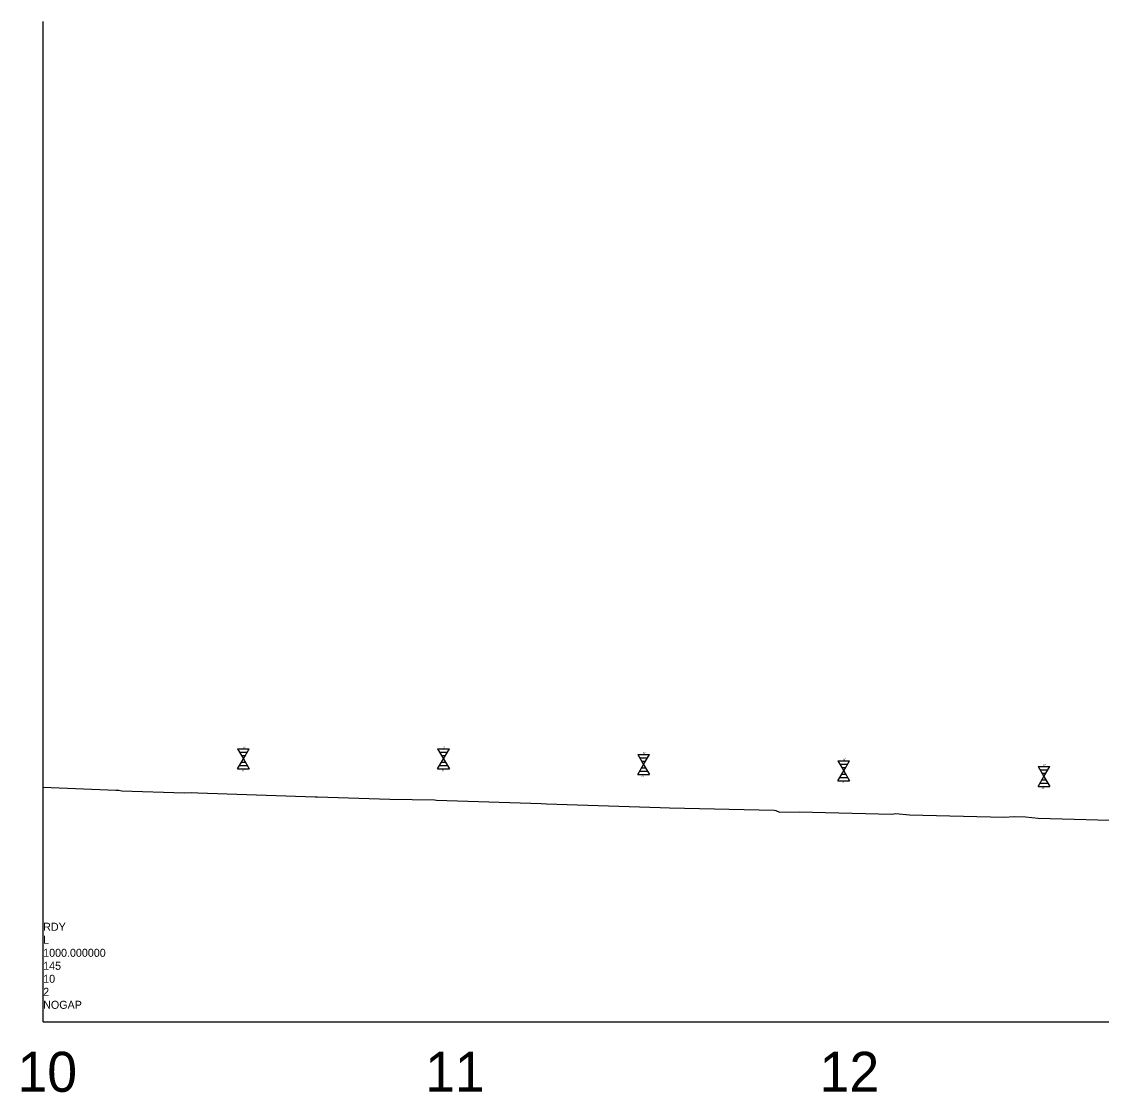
# Model space of a CAD drawing. Extents: x 573468 to 580768, y -57414 to -51768.
# Drawn here: x 573759.8 to 574029.6, y -53116.2 to -52848.5 of the extents above; entities that cross this region are included whole.
import ezdxf

# ---------------------------------------------------------------- set-up
doc = ezdxf.new("R2010")
doc.units = 0
for name, color, linetype in [('Exist Profile Cell', 7, 'Continuous'), ('Exist Vertical Profile Ground Line', 7, 'Continuous'), ('Exist Vertical Profile Horizontal Axis Label Major', 7, 'Continuous'), ('Scratch_Level_0', 7, 'Continuous')]:
    doc.layers.add(name, color=color, linetype=linetype)

msp = doc.modelspace()

# ---------------------------------------------------------------- linework, layer by layer
at = {"layer": 'Exist Profile Cell'}
for q in [(573765.21, -52848.54), (577467.91, -53098.54), (573765.21, -53098.54)]:
    msp.add_line((573765.21, -53098.54), q, dxfattribs=at)
at = {"layer": 'Exist Vertical Profile Ground Line'}
msp.add_lwpolyline([(573765.21, -53039.89), (573783.39, -53040.63), (573784.13, -53040.65), (573784.87, -53040.81), (573800.44, -53041.29), (573802.37, -53041.25), (573803.85, -53041.29), (573833.18, -53042.27), (573833.76, -53042.29), (573851.8, -53042.89), (573862.99, -53043.1), (573863.5, -53043.12), (573889.61, -53043.98), (573890.92, -53044.02), (573919.38, -53044.96), (573921.69, -53045.02), (573947.83, -53045.68), (573948.23, -53045.69), (573949.12, -53046.11), (573954.03, -53046.03), (573977.23, -53046.63), (573978.18, -53046.46), (573981.66, -53046.78), (574005.22, -53047.4), (574007.92, -53047.25), (574010.63, -53047.33), (574013.74, -53047.68), (574037.65, -53048.31)], dxfattribs=at)
at = {"layer": 'Scratch_Level_0'}
for p, q in [((573813.75, -53030.34), (573816.68, -53030.34)), ((573813.75, -53030.34), (573815.21, -53032.84)), ((573814.24, -53031.18), (573816.19, -53031.18)), ((573815.21, -53032.84), (573816.68, -53030.34)), ((573863.75, -53030.34), (573866.68, -53030.34)), ((573863.75, -53030.34), (573865.21, -53032.84)), ((573864.24, -53031.18), (573866.19, -53031.18)), ((573865.21, -53032.84), (573866.68, -53030.34)), ((573813.75, -53035.34), (573815.21, -53032.84)), ((573814.73, -53032.01), (573815.7, -53032.01)), ((573814.73, -53033.68), (573815.7, -53033.68)), ((573815.21, -53032.84), (573816.68, -53035.34)), ((573863.75, -53035.34), (573865.21, -53032.84)), ((573864.73, -53032.01), (573865.7, -53032.01)), ((573864.73, -53033.68), (573865.7, -53033.68)), ((573865.21, -53032.84), (573866.68, -53035.34)), ((573913.75, -53031.71), (573916.68, -53031.71)), ((573913.75, -53031.71), (573915.21, -53034.21)), ((573914.24, -53032.54), (573916.19, -53032.54)), ((573914.73, -53033.38), (573915.7, -53033.38)), ((573915.21, -53034.21), (573916.68, -53031.71)), ((573963.75, -53033.28), (573966.68, -53033.28)), ((573963.75, -53033.28), (573965.21, -53035.78)), ((573965.21, -53035.78), (573966.68, -53033.28)), ((573813.75, -53035.34), (573816.68, -53035.34)), ((573814.24, -53034.51), (573816.19, -53034.51)), ((573863.75, -53035.34), (573866.68, -53035.34)), ((573864.24, -53034.51), (573866.19, -53034.51)), ((573913.75, -53036.71), (573915.21, -53034.21)), ((573913.75, -53036.71), (573916.68, -53036.71)), ((573914.24, -53035.88), (573916.19, -53035.88)), ((573914.73, -53035.04), (573915.7, -53035.04)), ((573915.21, -53034.21), (573916.68, -53036.71)), ((573963.75, -53038.28), (573965.21, -53035.78)), ((573964.24, -53034.11), (573966.19, -53034.11)), ((573964.73, -53034.95), (573965.7, -53034.95)), ((573964.73, -53036.61), (573965.7, -53036.61)), ((573965.21, -53035.78), (573966.68, -53038.28)), ((574013.75, -53034.73), (574016.68, -53034.73)), ((574013.75, -53034.73), (574015.21, -53037.23)), ((574014.24, -53035.57), (574016.19, -53035.57)), ((574014.73, -53036.4), (574015.7, -53036.4)), ((574015.21, -53037.23), (574016.68, -53034.73)), ((573963.75, -53038.28), (573966.68, -53038.28)), ((573964.24, -53037.45), (573966.19, -53037.45)), ((574013.75, -53039.73), (574015.21, -53037.23)), ((574014.24, -53038.9), (574016.19, -53038.9)), ((574014.73, -53038.07), (574015.7, -53038.07)), ((574015.21, -53037.23), (574016.68, -53039.73)), ((574013.75, -53039.73), (574016.68, -53039.73))]:
    msp.add_line(p, q, dxfattribs=at)

# ---------------------------------------------------------------- texts
at = {"layer": 'Exist Profile Cell'}
for s, p in [('RDY', (573765.21, -53075.79)), ('L', (573765.21, -53079.04)), ('1000.000000', (573765.21, -53082.29)), ('145', (573765.21, -53085.54)), ('10', (573765.21, -53088.79)), ('2', (573765.21, -53092.04)), ('NOGAP', (573765.21, -53095.29))]:
    msp.add_text(s, height=2, dxfattribs=at).set_placement(p)
at = {"layer": 'Exist Vertical Profile Horizontal Axis Label Major'}
for s, p in [('10', (573758.8, -53116.04)), ('11', (573860.64, -53116.04)), ('12', (573959.19, -53116.04))]:
    msp.add_text(s, height=10, dxfattribs=at).set_placement(p)
at = {"layer": 'Scratch_Level_0'}
for s, p in [('6"', (573815.1, -53030.24)), ('6"', (573865.1, -53030.24)), ('6"', (573915.1, -53031.61)), ('6"', (573965.1, -53033.18)), ('-6"', (573814.64, -53035.95)), ('-6"', (573864.64, -53035.95)), ('6"', (574015.1, -53034.63)), ('-6"', (573914.64, -53037.31)), ('-6"', (573964.64, -53038.88)), ('-6"', (574014.64, -53040.34))]:
    msp.add_text(s, height=0.5, dxfattribs=at).set_placement(p)

doc.saveas('drawing.dxf')
